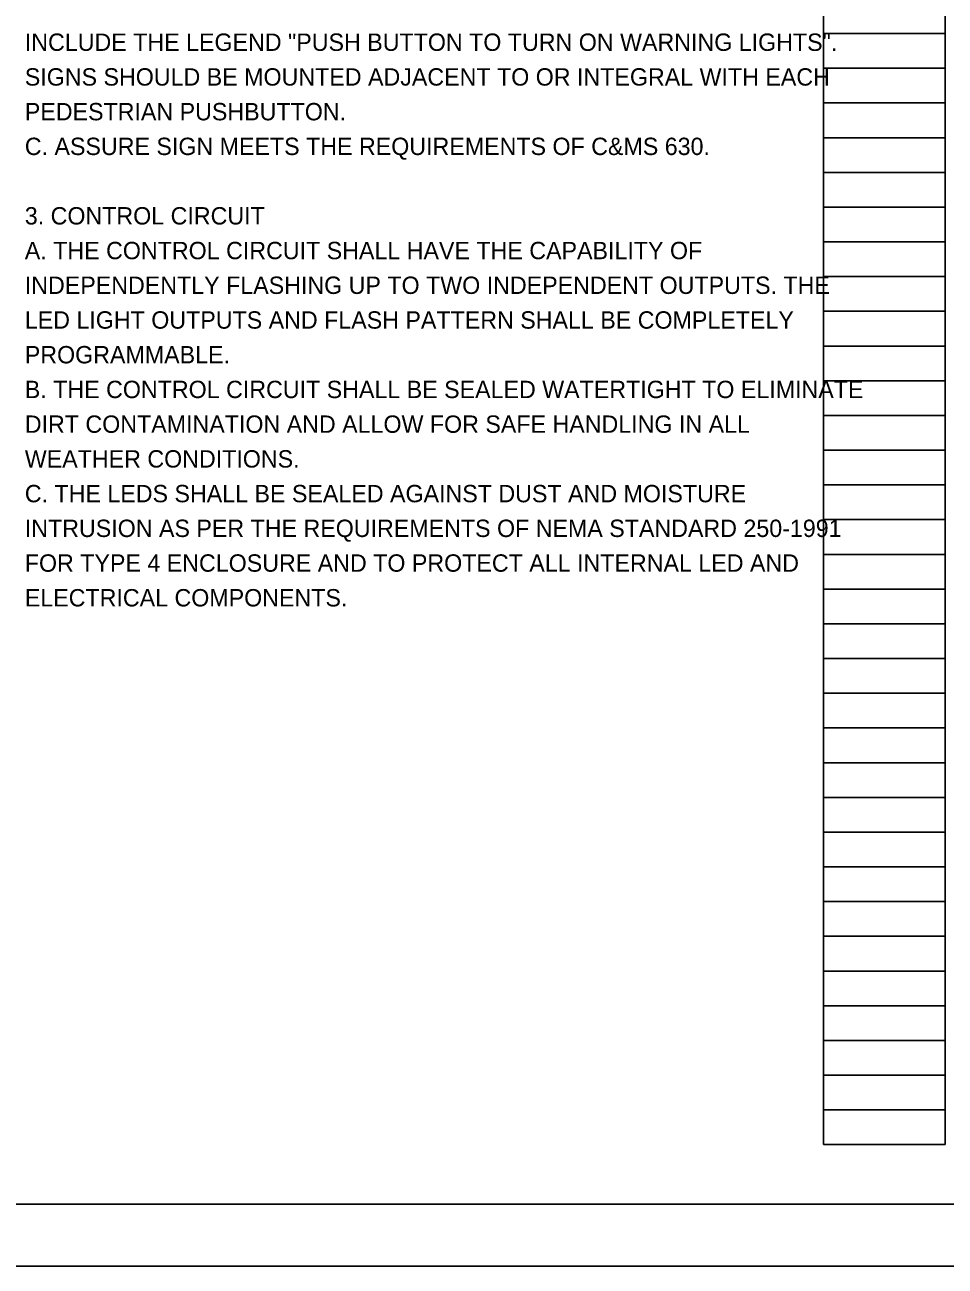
# Model space of a CAD drawing. Extents: x 0 to 34, y 0 to 22.
# Drawn here: x 17.24 to 24.66, y 0 to 10.01 of the extents above; entities that cross this region are included whole.
import ezdxf

# ---------------------------------------------------------------- set-up
doc = ezdxf.new("R2010")
doc.units = 0
for name, color, linetype in [('SH_Border', 7, 'Continuous'), ('SH_Cut_Line', 7, 'Continuous'), ('SH_Data', 7, 'Continuous'), ('SH_Text', 7, 'Continuous')]:
    doc.layers.add(name, color=color, linetype=linetype)

msp = doc.modelspace()

# ---------------------------------------------------------------- linework, layer by layer
at = {"layer": 'SH_Border'}
msp.add_lwpolyline([(1.5, 21.5), (33.5, 21.5), (33.5, 0.5), (1.5, 0.5)], close=True, dxfattribs=at)
at = {"layer": 'SH_Cut_Line'}
msp.add_lwpolyline([(0, 0), (34, 0), (34, 22), (0, 22)], close=True, dxfattribs=at)
at = {"layer": 'SH_Data'}
for p, q in [((23.68, 0.98), (23.68, 21.14)), ((24.66, 0.98), (24.66, 21.14)), ((23.68, 9.94), (24.66, 9.94)), ((23.68, 9.66), (24.66, 9.66)), ((23.68, 9.38), (24.66, 9.38)), ((23.68, 9.1), (24.66, 9.1)), ((23.68, 8.82), (24.66, 8.82)), ((23.68, 8.54), (24.66, 8.54)), ((23.68, 8.26), (24.66, 8.26)), ((23.68, 7.98), (24.66, 7.98)), ((23.68, 7.7), (24.66, 7.7)), ((23.68, 7.42), (24.66, 7.42)), ((23.68, 7.14), (24.66, 7.14)), ((23.68, 6.86), (24.66, 6.86)), ((23.68, 6.58), (24.66, 6.58)), ((23.68, 6.3), (24.66, 6.3)), ((23.68, 6.02), (24.66, 6.02)), ((23.68, 5.74), (24.66, 5.74)), ((23.68, 5.46), (24.66, 5.46)), ((23.68, 5.18), (24.66, 5.18)), ((23.68, 4.9), (24.66, 4.9)), ((23.68, 4.62), (24.66, 4.62)), ((23.68, 4.34), (24.66, 4.34)), ((23.68, 4.06), (24.66, 4.06)), ((23.68, 3.78), (24.66, 3.78)), ((23.68, 3.5), (24.66, 3.5)), ((23.68, 3.22), (24.66, 3.22)), ((23.68, 2.94), (24.66, 2.94)), ((23.68, 2.66), (24.66, 2.66)), ((23.68, 2.38), (24.66, 2.38)), ((23.68, 2.1), (24.66, 2.1)), ((23.68, 1.82), (24.66, 1.82)), ((23.68, 1.54), (24.66, 1.54)), ((23.68, 1.26), (24.66, 1.26)), ((23.68, 0.98), (24.66, 0.98))]:
    msp.add_line(p, q, dxfattribs=at)

# ---------------------------------------------------------------- texts
at = {"layer": 'SH_Text'}
for s, p in [('INCLUDE THE LEGEND "PUSH BUTTON TO TURN ON WARNING LIGHTS". ', (17.24, 9.8)), ('SIGNS SHOULD BE MOUNTED ADJACENT TO OR INTEGRAL WITH EACH ', (17.24, 9.52)), ('PEDESTRIAN PUSHBUTTON.', (17.24, 9.24)), ('C. ASSURE SIGN MEETS THE REQUIREMENTS OF C&MS 630.', (17.24, 8.96)), ('3. CONTROL CIRCUIT', (17.24, 8.4)), ('A. THE CONTROL CIRCUIT SHALL HAVE THE CAPABILITY OF ', (17.24, 8.12)), ('INDEPENDENTLY FLASHING UP TO TWO INDEPENDENT OUTPUTS. THE ', (17.24, 7.84)), ('LED LIGHT OUTPUTS AND FLASH PATTERN SHALL BE COMPLETELY ', (17.24, 7.56)), ('PROGRAMMABLE.', (17.24, 7.28)), ('B. THE CONTROL CIRCUIT SHALL BE SEALED WATERTIGHT TO ELIMINATE ', (17.24, 7)), ('DIRT CONTAMINATION AND ALLOW FOR SAFE HANDLING IN ALL ', (17.24, 6.72)), ('WEATHER CONDITIONS.', (17.24, 6.44)), ('C. THE LEDS SHALL BE SEALED AGAINST DUST AND MOISTURE ', (17.24, 6.16)), ('INTRUSION AS PER THE REQUIREMENTS OF NEMA STANDARD 250-1991 ', (17.24, 5.88)), ('FOR TYPE 4 ENCLOSURE AND TO PROTECT ALL INTERNAL LED AND ', (17.24, 5.6)), ('ELECTRICAL COMPONENTS.', (17.24, 5.32))]:
    msp.add_text(s, height=0.14, dxfattribs=at).set_placement(p)

doc.saveas('drawing.dxf')
